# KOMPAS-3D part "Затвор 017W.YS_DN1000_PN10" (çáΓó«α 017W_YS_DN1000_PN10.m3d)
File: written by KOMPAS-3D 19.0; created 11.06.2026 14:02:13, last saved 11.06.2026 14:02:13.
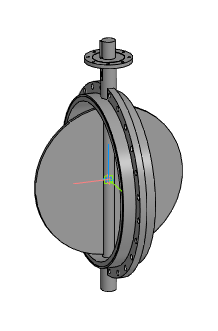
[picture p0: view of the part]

Document properties: Автор: Евгений; Полное имя файла: Z:\3.Личные\kachalov\001_3d для проектировщиков\x.x Тип 017W.Y(S) Затвор дисковый поворотный межфланцевый\_stp_Затвор 017W.YS_DN32-DN1200\Затвор 017W_YS_DN1000_PN10.m3d

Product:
- Part/product: Затвор 017W.YS_DN1000_PN10

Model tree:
1. Операция без истории:1  (labels: Затвор 017W.YS_DN1000_PN10)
